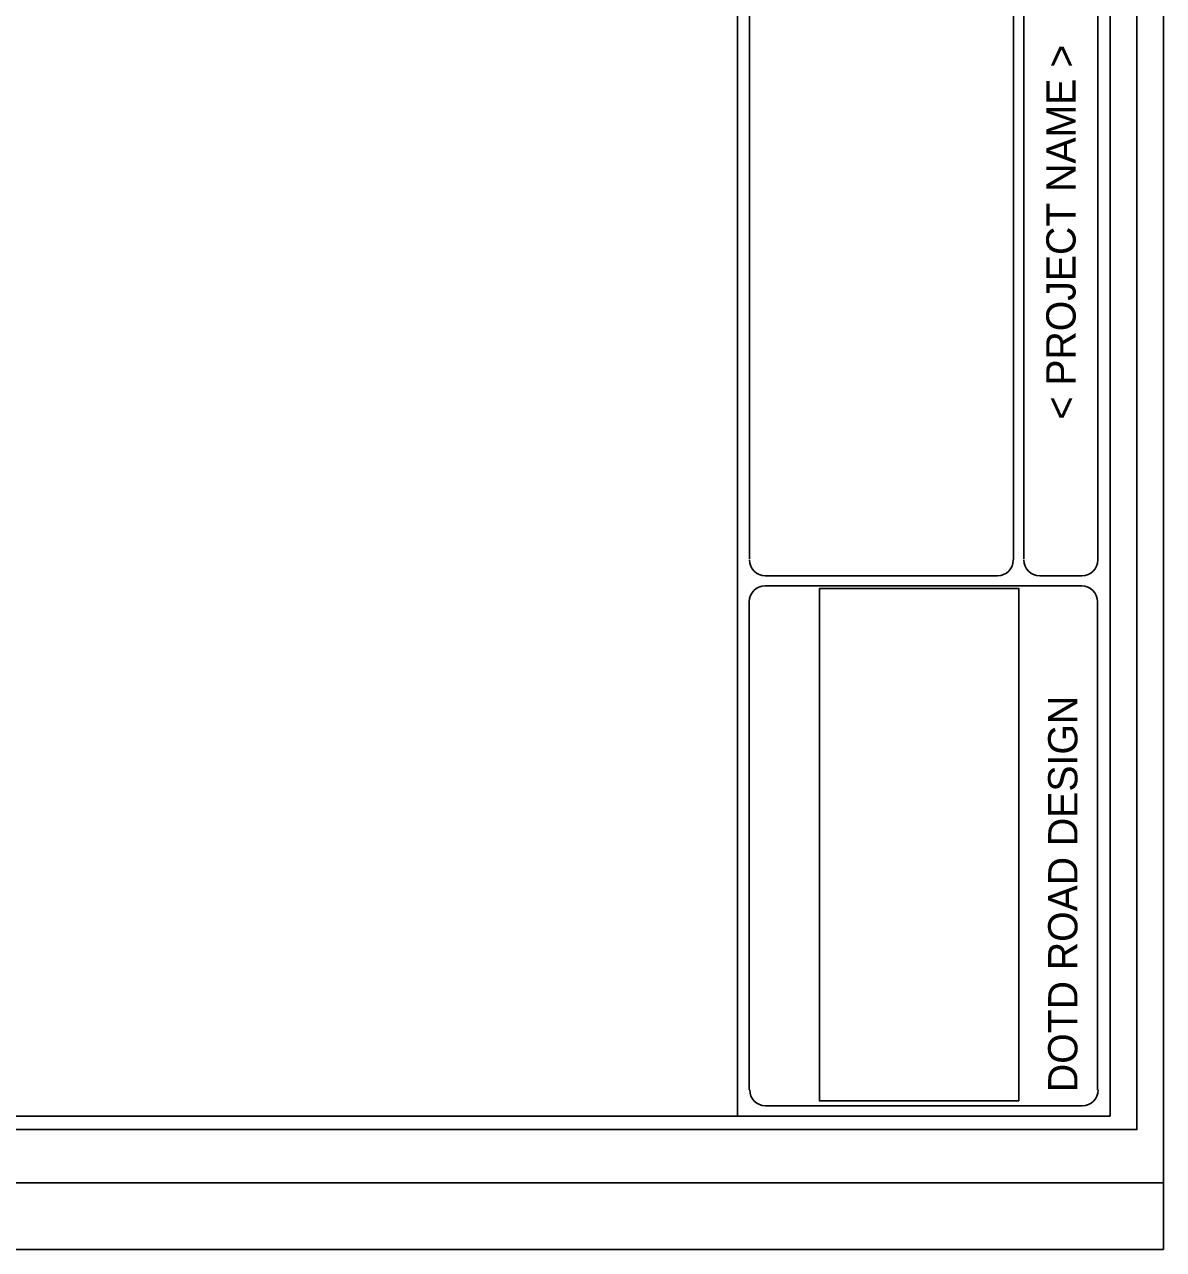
# Model space of a CAD drawing. Extents: x -0.02 to 2.83, y -0.02 to 1.85.
# Drawn here: x 2.477 to 2.8333, y 0 to 0.3832 of the extents above; entities that cross this region are included whole.
import ezdxf

# ---------------------------------------------------------------- set-up
doc = ezdxf.new("R2010")
doc.units = 0
for name, color, linetype in [('Plot Border', 7, 'Continuous'), ('Plot Border 2', 7, 'Continuous'), ('Seal', 7, 'Continuous'), ('Sheet Border', 7, 'Continuous')]:
    doc.layers.add(name, color=color, linetype=linetype)

msp = doc.modelspace()

# ---------------------------------------------------------------- linework, layer by layer
at = {"layer": 'Plot Border'}
for points in [[(0, 1.83333), (2.83333, 1.83333), (2.83333, 0), (0, 0)], [(2.825, 1.79583), (0.075, 1.79583), (0.075, 0.0375), (2.825, 0.0375)]]:
    msp.add_lwpolyline(points, close=True, dxfattribs=at)
at = {"layer": 'Plot Border 2'}
msp.add_lwpolyline([(0, 1.8125), (2.83333, 1.8125), (2.83333, 0.02083), (0, 0.02083)], close=True, dxfattribs=at)
at = {"layer": 'Seal'}
msp.add_lwpolyline([(2.7881, 0.04647), (2.7881, 0.20674), (2.72565, 0.20674), (2.72565, 0.04647)], close=True, dxfattribs=at)
at = {"layer": 'Sheet Border'}
for p, q in [((2.7, 1.79167), (2.7, 0.04167)), ((2.81667, 1.79167), (2.81667, 0.04167)), ((2.70381, 0.57905), (2.70381, 0.21605)), ((2.70381, 0.57905), (2.70381, 0.21605)), ((2.78636, 0.57868), (2.78636, 0.21568)), ((2.78966, 0.57905), (2.78966, 0.21605)), ((2.81277, 0.57868), (2.81277, 0.21568)), ((2.80774, 0.20755), (2.70868, 0.20755)), ((2.78141, 0.21073), (2.70876, 0.21073)), ((2.80782, 0.21073), (2.79461, 0.21073)), ((2.70373, 0.20259), (2.70373, 0.04992)), ((2.81269, 0.20259), (2.81269, 0.04992)), ((2.8079, 0.04497), (2.70881, 0.04497)), ((0.19167, 0.04167), (2.81667, 0.04167))]:
    msp.add_line(p, q, dxfattribs=at)
for centre, start, end in [((2.70875, 0.21568), 180, 270), ((2.78139, 0.21568), 270, 0), ((2.7946, 0.21568), 180, 270), ((2.80781, 0.21568), 270, 0), ((2.70869, 0.20261), 90, 180), ((2.80775, 0.20261), 0, 90), ((2.70881, 0.04992), 180, 270), ((2.8079, 0.04992), 270, 360)]:
    msp.add_arc(centre, 0.00495, start, end, dxfattribs=at)

# ---------------------------------------------------------------- texts
for s, height, p in [('               < PROJECT NAME >               ', 0.0091667, (2.80582, 0.20854)), (' DOTD ROAD DESIGN', 0.0091666, (2.8064, 0.04583))]:
    msp.add_text(s, height=height, rotation=90, dxfattribs=at).set_placement(p)

doc.saveas('drawing.dxf')
